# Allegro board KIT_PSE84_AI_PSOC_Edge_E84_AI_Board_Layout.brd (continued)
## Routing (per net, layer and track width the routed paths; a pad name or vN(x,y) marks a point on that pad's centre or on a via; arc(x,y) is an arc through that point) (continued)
RF_OUT: length 2
  TOP w0.127: C198.1 U25.50
ROSC_IN_80MHZ: length 2.2
  TOP w0.15: R102.2 21.77,17.37 22.28,17.89 U5.M2
RSPI_CLK: length 18.4
  TOP w0.089: v1(23.96,30.11) 24.24,30.39 U1.L7
  TOP w0.102: v2(30.57,19.06) 30.3,18.79 30.08,18.79 29.9,18.97
  TOP w0.15: U5.B1 28.83,19.29 29.58,19.29 29.9,18.97
  L03_SIG1 w0.089: v2(24.84,23.88) 24.84,25.57 24.52,25.89 24.52,28.46 24.29,28.7 24.29,29.78 v1(23.96,30.11)
  L05_PWR w0.102: v2(24.84,23.88) 25.78,22.94 25.93,22.94 26.14,22.73 26.14,22.58 28.95,19.77 30.27,19.77 30.49,19.55 30.49,19.55 30.57,19.47 v2(30.57,19.06)
RSPI_CS: length 27.1
  TOP w0.089: v1(21.26,35.94) 21.29,35.94 21.31,35.92 21.33,35.92 U1.C3
  TOP w0.15: v2(29.54,20.75) 29.54,20.77 29.23,21.08 27.63,21.08 27.48,20.93 27.48,20.22 26.59,19.33 26.37,19.33 U5.G1
  L03_SIG1 w0.089: v1(21.26,35.94) 20.99,35.67 20.99,35.15 21.18,34.96 21.45,34.96 21.64,34.77 21.64,34.49 21.82,34.31 22.1,34.31 22.29,34.12 22.29,33.85 22.48,33.66 23.81,33.66 24.43,33.04 24.69,33.04 24.96,32.77 24.96,32.3 24.86,32.21 24.86,31.92 24.99,31.79 24.99,31.31 24.64,30.95 24.64,30.54 24.87,30.31 24.87,28.63 24.93,28.58 24.93,26.96 24.94,26.96
  L03_SIG1 w0.102: v2(26.44,23.88) 26.17,24.15 26.17,25.54 25.68,26.04 25.18,26.04 24.94,26.28 24.94,26.68 24.94,26.96
  L05_PWR w0.102: v2(26.44,23.88) 29.27,21.05 29.27,21.02 v2(29.54,20.75)
RSPI_IRQ: length 15.9
  TOP w0.089: U1.N12 27.83,28.78 v1(27.83,28.75)
  TOP w0.15: U5.C1 28.64,19.6 29.85,19.6 30.05,19.39 v2(30.11,19.39)
  L03_SIG1 w0.089: 29.9,26.59 29.9,26.83 28.99,27.75 28.37,27.75 28.16,27.96 28.16,28.17 27.83,28.5 v1(27.83,28.75)
  L03_SIG1 w0.157: 29.9,26.59 30.53,25.97 30.53,23.88 30.74,23.67 30.74,21.69 31.3,21.13 31.3,19.79 31.09,19.58 30.3,19.58 30.11,19.39 v2(30.11,19.39)
RSPI_MISO: length 21.2
  TOP w0.089: v1(23.94,31.37) 23.91,31.37 U1.K6
  TOP w0.102: 29.51,20.17 29.99,20.17 30.13,20.03 30.47,20.03 30.56,19.94 v2(30.94,19.94)
  TOP w0.15: U5.E1 28.21,20.17 29.51,20.17
  L03_SIG1 w0.089: v2(25.66,23.88) 25.03,24.5 25.03,25.67 24.71,25.99 24.71,28.54 24.48,28.77 24.48,30.11 24.28,30.31 24.28,31.03 v1(23.94,31.37)
  L05_PWR w0.089: 26.06,23.09 26.06,23.46 25.92,23.6 25.92,23.61 v2(25.66,23.88)
  L05_PWR w0.102: v2(30.94,19.94) 30.67,20.21 28.94,20.21 26.06,23.09
RSPI_MOSI: length 45
  TOP w0.089: U1.C5 v1(22.62,35.94)
  TOP w0.15: U5.D1 28.39,19.85 29.95,19.85 30.01,19.8 30.28,19.8 30.61,19.47 30.89,19.47 31.05,19.31 31.05,19.14 30.98,19.06 v2(30.98,18.66)
  L03_SIG1 w0.089: v1(22.62,35.94) 22.62,36.13 22.29,36.45 22.29,36.73 22.1,36.92 21.83,36.92 20.76,37.99 20.16,37.99 20.08,37.91 19.43,37.91 19.13,37.61 19.13,35.85 20.68,34.31 21.45,34.31 21.64,34.12 21.64,33.85 21.84,33.66 22.1,33.66 22.29,33.47 22.29,33.2 22.48,33.01 22.75,33.01 23.15,33.41 23.6,33.41 23.9,33.1 v1(23.9,32.05)
  L04_SIG2 w0.089: 24.13,26.59 24.39,26.85 24.39,27.77 24.45,27.83 24.45,30.99 24.26,31.18 24.26,31.63 24.15,31.75 24.15,31.8 v1(23.9,32.05)
  L04_SIG2 w0.157: v2(21.02,20.04) 21.02,20.25 20.61,20.66 20.61,21 20.85,21.24 21.02,21.24 22.34,22.56 22.34,22.96 23.02,23.64 23.02,24.07 23.47,24.52 23.47,25.93 24.13,26.59
  L05_PWR w0.178: v2(30.98,18.66) 30.75,18.43 28.76,18.43 27.15,20.04 v2(21.02,20.04)
RXRES_L: length 9
  TOP w0.15: v2(28.98,20.68) 28.9,20.59 R101.1 ; U1.R12 27.56,27.75 27.56,27.38 27.84,27.1 v2(27.86,27.1)
  L03_SIG1 w0.102: v2(27.86,27.1) 28.21,26.76 28.21,26.3 29.35,25.16 29.35,24.8 29.77,24.38 29.77,24.03 29.41,23.67 29.41,23.24
  L03_SIG1 w0.157: v2(28.98,20.68) 28.98,22.82 29.41,23.24
SERIAL_INT0: length 21.1
  TOP w0.15: U1.L14 v1(29.12,30.09)
  L04_SIG2 w0.089: 31.17,30.46 30.89,30.46 30.52,30.09 v1(29.12,30.09)
  L04_SIG2 w0.157: 31.17,30.46 32.25,31.54 32.25,32.34 32.91,32.99 32.91,39.59 J5.5
  BOTTOM w0.15: J5.5 32.77,39.45 32.77,36.71 32.53,36.47 32.53,35.93 32.62,35.84 R192.1
SERIAL_INT1: length 18.9
  TOP w0.15: U1.M13 v1(28.49,29.41)
  L04_SIG2 w0.089: v1(28.49,29.41) 29.46,29.41
  L04_SIG2 w0.157: 29.46,29.41 29.8,29.41 30.05,29.66 31.26,29.66 31.37,29.77 32.35,29.77 32.51,29.93 32.51,32.23 33.17,32.89 33.17,37.31 J5.4
  BOTTOM w0.15: J5.4 33.1,37.24 33.1,34.86 32.92,34.69 R193.1
SERIAL_INT2: length 15.6
  TOP w0.15: U1.M14 29.09,29.47 29.64,29.47 29.82,29.29 v1(30.2,29.29)
  L04_SIG2 w0.089: 31.17,28.9 30.78,29.29 v1(30.2,29.29)
  L04_SIG2 w0.157: 31.17,28.9 31.62,28.45 32.01,28.45 32.41,28.85 32.41,29.39 32.89,29.87 32.89,31.49 33.43,32.02 33.43,35.03 J5.3
  BOTTOM w0.15: J5.3 34.42,35.04 33.27,33.89 R194.1
SERIAL_INT3: length 14
  TOP w0.15: U1.N13 28.47,28.79 v1(28.49,28.79)
  L04_SIG2 w0.089: 31.17,28.12 30.24,28.12 29.91,28.45 28.83,28.45 v1(28.49,28.79)
  L04_SIG2 w0.157: J5.2 35.36,32.54 35.36,30.55 34.7,29.89 33.85,29.89 33.29,29.33 33.29,29.15 32.26,28.12 31.17,28.12
  BOTTOM w0.15: J5.2 33.44,33.48 33.05,33.09 R195.1
SMIF0_CLKP: length 4.5
  BOTTOM w0.15: U4.B2 12.66,37.61 12.83,37.44 12.83,35.82 13.77,34.88 R61.1
SMIF0_CS: length 32.3
  TOP w0.15: v2(11.39,38.11) 10.33,39.17 R112.1 6.38,39.17 5.59,38.38 5.59,33.3 6.4,32.49 6.48,32.49 6.5,32.46 7.31,32.46 10.69,29.08 17.09,29.08 17.4,28.77 18.51,28.77 18.74,29 18.74,29.64 19,29.9 19,30.34 19.43,30.77 22,30.77 U1.K4
  BOTTOM w0.15: U4.C2 11.39,37.69 v2(11.39,38.11)
SMIF0_DATA0: length 7.1
  BOTTOM w0.15: U4.D3 10.3,39.03 10.45,39.18 10.7,39.18 10.85,39.03 10.85,35.76 11,35.61 11.51,35.61 12.04,35.08 R45.1
SMIF0_DATA1: length 4.6
  BOTTOM w0.15: R47.1 11.06,34.79 9.91,35.94 9.91,37.46 10.06,37.61 U4.D2
SMIF0_DATA2: length 8.2
  BOTTOM w0.15: U4.C4 11.05,39.61 10.9,39.76 10.9,40.03 11.05,40.18 11.26,40.18 11.84,39.6 11.84,35.82 12.83,34.82 12.83,33.88 R49.1
SMIF0_DATA3: length 7.7
  BOTTOM w0.15: U4.D4 9.81,39.12 9.04,39.12 8.5,38.57 8.5,35.99 10.16,34.33 R51.1
SMIF1_CLKN: length 12.8
  TOP w0.102: R63.2 16.97,33.82 16.75,34.04 16.12,34.04 15.83,34.34 15.72,34.34 v2(15.47,34.08) ; v2(8.91,36.16) 9.16,36.42 9.97,36.42 10.07,36.32 10.07,35.9 9.97,35.8 U3.B1
  L03_SIG1 w0.102: v2(15.47,34.08) 15.47,34.23 15.36,34.33 15.08,34.33 14.78,34.03 13.31,34.03 13.13,33.85 12.83,33.85 12.65,34.03 12.15,34.03 11.96,33.85 11.66,33.85 11.48,34.03 11.17,34.03 10.39,34.81 10.13,34.81 9.92,35.02 9.92,35.28 9.7,35.49 9.7,36.03 9.33,36.4 9.01,36.4 8.91,36.3 v2(8.91,36.16)
SMIF1_CLKP: length 12.8
  TOP w0.102: v2(15.47,34.85) 15.72,34.6 15.93,34.6 16.23,34.3 16.82,34.3 16.97,34.45 R62.2 ; U3.B2 10.43,35.8 10.33,35.9 10.33,36.42 10.07,36.67 9.16,36.67 v2(8.91,36.93)
  L03_SIG1 w0.102: v2(15.47,34.85) 15.47,34.71 15.36,34.61 14.96,34.61 14.66,34.31 11.28,34.31 9.98,35.61 9.98,36.15 9.44,36.69 9.01,36.69 8.91,36.79 v2(8.91,36.93)
SMIF1_CS: length 32.3
  TOP w0.15: U1.C4 21.98,35.92 v1(21.95,35.92) ; U3.A3 11.35,36.8 10.68,37.46 7.9,37.46 7.73,37.29 R114.1 6.68,37.29 5.84,36.45 5.84,33.48 6.6,32.72 7.44,32.72 9.8,30.36 v2(11.56,30.36)
  L04_SIG2 w0.089: 20.76,36.21 20.84,36.29 21.45,36.29 21.64,36.48 21.64,36.83 21.73,36.92 22.1,36.92 22.29,36.73 22.29,36.25 22.2,36.17 22.2,36.17 v1(21.95,35.92)
  L04_SIG2 w0.157: 20.76,36.21 18.94,36.21 16.26,33.53 16.26,33.36 15.95,33.05 15.95,32.1 15.5,31.65 12.85,31.65 v2(11.56,30.36)
SMIF1_DATA0: length 11.5
  TOP w0.15: v2(15.75,37.29) 16.23,37.77 R46.2 ; v1(12.35,36.13) 12.17,35.95 12.17,34.7 11.7,34.23 U3.D3
  L03_SIG1 w0.157: v2(15.75,37.29) 15.67,37.36 13.59,37.36 13.31,37.64 11.13,37.64 10.95,37.46 10.95,37.19 11.11,37.03 12.12,37.03 12.34,36.81 12.34,36.52 12.35,36.51 v1(12.35,36.13)
SMIF1_DATA1: length 12.6
  TOP w0.15: R48.2 16.88,37.06 16.38,37.06 16.11,36.78 15.45,36.78 v2(15.32,36.91) ; v1(11.16,35.23) 11.1,35.17 11.1,34.7 10.7,34.3 U3.D2
  L03_SIG1 w0.157: v1(11.16,35.23) 11.16,35.33 10.38,36.1 10.38,36.31 9.87,36.82 9.87,37.04 10.06,37.24 10.29,37.24 10.89,36.64 11.32,36.64 11.69,36.26 11.69,36.21 12.17,35.73 12.5,35.73 12.69,35.92 13.49,35.92 13.87,36.3 13.87,36.38 14.33,36.84 14.41,36.84 14.48,36.91 v2(15.32,36.91)
SMIF1_DATA2: length 11.2
  TOP w0.15: v2(16.01,36.35) 16.01,36.24 16.44,35.82 16.65,35.82 16.97,36.14 R50.2 ; v1(13.21,34.88) 13.21,35.23 13.06,35.38 12.85,35.38 12.7,35.23 U3.C4
  L03_SIG1 w0.157: v1(13.21,34.88) 12.83,34.88 12.7,34.75 11.81,34.75 11.65,34.91 11.65,35.13 11.81,35.29 13.07,35.29 13.29,35.51 13.7,35.51 13.92,35.29 14.23,35.29 14.49,35.55 14.49,35.77 14.27,35.99 14.27,36.22 14.49,36.44 14.72,36.44 15.3,35.86 15.85,35.86 16.01,36.02 v2(16.01,36.35)
SMIF1_DATA3: length 11.6
  TOP w0.15: U3.D4 12.62,33.72 12.33,33.72 12.18,33.87 12.18,34.15 12.4,34.37 14.2,34.37 14.5,34.67 v1(14.5,34.77) ; v2(15.77,35.37) 15.66,35.26 15.3,35.26 15.19,35.15 14.25,35.15 14.07,35.33 14.07,35.61 14.25,35.79 14.71,35.79 14.86,35.94 14.86,36.27 15.01,36.42 15.27,36.42 15.45,36.24 15.45,35.94 15.62,35.78 15.94,35.78 16.18,35.54 16.18,35.41 16.34,35.25 16.85,35.25 R52.2
  L03_SIG1 w0.157: v1(14.5,34.77) 14.5,35 14.97,35.46 15.68,35.46 v2(15.77,35.37)
SMIF1_DATA4: length 11.7
  TOP w0.15: R54.2 v2(16.31,32.17) ; v1(14.33,33.66) 14.33,33.96 14.48,34.11 14.69,34.11 14.84,33.96 14.84,32.6 15.01,32.42 15.01,31.82 14.74,31.55 14.3,31.55 14.15,31.7 14.15,31.93 14.5,32.28 14.5,32.79 14.12,33.17 13.23,33.17 13.08,33.32 13.08,33.78 13.21,33.92 13.58,33.92 U3.D5
  L03_SIG1 w0.157: v2(16.31,32.17) 16.02,32.46 16.02,32.81 15.17,33.66 v1(14.33,33.66)
SMIF1_DATA5: length 11.4
  TOP w0.15: v1(12.27,32.39) 12.24,32.36 11.4,32.36 11.25,32.51 11.25,32.69 11.36,32.8 U3.E3 ; v2(15.24,32.76) 15.25,32.76 16.02,32.76 16.23,32.97 R56.2
  L03_SIG1 w0.157: v1(12.27,32.39) 12.8,32.39 12.91,32.28 12.91,32.1 12.64,31.83 12.3,31.83 11.63,32.49 11.63,32.85 12.37,33.58 12.57,33.58 12.85,33.3 12.85,33.08 13.01,32.92 13.32,32.92 13.48,33.08 13.48,33.27 13.64,33.43 13.99,33.43 14.16,33.26 14.75,33.26 v2(15.24,32.76)
SMIF1_DATA6: length 11.6
  TOP w0.15: R58.2 16.72,31.42 16.44,31.7 15.47,31.7 v2(15.04,31.27) ; U3.E2 v1(10.22,32.8)
  L03_SIG1 w0.157: v2(15.04,31.27) 14.45,31.85 13.79,31.85 12.7,30.76 12.23,30.76 11.75,31.24 10.95,31.24 9.68,32.51 9.68,33.49 9.79,33.61 10.04,33.61 10.19,33.45 10.19,32.82 v1(10.22,32.8)
SMIF1_DATA7: length 11.3
  TOP w0.15: v2(15.62,29.49) 15.9,29.77 R60.2 ; U3.E1 9.69,32.79 9.27,32.79 9.27,32.79 v1(9.22,32.79)
  L03_SIG1 w0.157: v1(9.22,32.79) 9.22,32.41 10.78,30.84 11.58,30.84 12.06,30.36 12.53,30.36 12.69,30.2 12.69,29.53 12.91,29.31 13.17,29.31 13.33,29.47 13.33,29.74 13.48,29.9 13.82,29.9 13.98,29.74 13.98,29.61 14.39,29.2 15.33,29.2 v2(15.62,29.49)
SMIF1_RWDS: length 12.4
  TOP w0.15: v2(15.83,31.24) 15.83,30.91 16.17,30.57 R65.2 ; U3.C3 11.7,34.76 11.32,34.38 11.32,33.56 v1(11.55,33.33)
  L03_SIG1 w0.157: v2(15.83,31.24) 14.81,32.25 14.81,32.62 14.57,32.86 13.98,32.86 13.72,32.59 13.72,32.34 12.65,31.27 12.28,31.27 11.32,32.24 10.82,32.24 10.64,32.41 10.64,33.15 10.83,33.33 v1(11.55,33.33)
USB_DEV_EN: length 21.6
  TOP w0.15: U31.4 14.9,14.23 15.05,14.08 15.05,13.87 15.02,13.83 v2(15.02,13.81) ; v2(15.43,19.17) 15.14,18.88 15.14,18.79 14.64,18.29 R219.1 ; Q3.5 17.44,6.48 17.98,7.02 17.98,8.25 17.62,8.61 17.17,8.61 16.54,7.98 v2(16.38,7.98)
  L03_SIG1 w0.157: v2(15.02,13.81) 15.02,15.56 14.76,15.83 14.76,17.2 15.43,17.87 v2(15.43,19.17)
  L04_SIG2 w0.157: v2(16.38,7.98) 16.09,8.27 16.06,8.27 15.59,8.74 15.59,9.68 14.78,10.49 14.78,13.17 15.02,13.41 v2(15.02,13.81)
  BOTTOM w0.15: v2(15.43,19.17) 15.43,19.13 15.58,18.97 U26.4 ; R191.2 17.15,7.21 17.12,7.18 16.78,7.18 16.38,7.58 v2(16.38,7.98)
USB_HOST_EN: length 19.4
  TOP w0.15: v2(14.52,13.5) 13.95,14.07 U31.3 ; U15.4 15.96,15.58 v2(15.82,15.44) 15.61,15.44 15.1,14.93 U31.6 ; v2(17.93,6.4) 18.01,6.48 Q3.2
  L03_SIG1 w0.157: v2(14.52,13.5) 14.81,13.21 15.31,13.21 15.46,13.36 15.46,15.08 v2(15.82,15.44)
  L04_SIG2 w0.157: v2(17.93,6.4) 18.36,6.83 18.36,8.31 17.55,9.12 17.07,9.12 15.37,10.82 15.37,11.56 15.46,11.65 15.46,15.08 v2(15.82,15.44)
  BOTTOM w0.15: v2(17.93,6.4) 17.81,6.28 R173.2
USB_V_SENSE: length 3.4
  BOTTOM w0.178: R27.2 R25.2 28.82,15.31 28.38,15.75 27.62,15.75 27.05,16.32 U2.19
USER_BTN: length 16.3
  TOP w0.15: U1.P3 v1(21.32,28.14) ; v2(16.46,23.34) 16.46,23.27 16.02,22.84 C57.1 15.58,22.84 15.47,22.73 SW1.2 SW1.1 9.73,22.73 9.63,22.64 R198.2
  L03_SIG1 w0.089: 20.6,26.59 21.07,27.06 21.07,27.89 v1(21.32,28.14)
  L03_SIG1 w0.157: v2(16.46,23.34) 17.14,24.02 19.54,24.02 20.37,24.85 20.37,25.99 20.6,26.23 20.6,26.59
USER_LED1: length 39.5
  TOP w0.15: Q7.G 30.51,7.61 30.71,7.42 R211.2 31.37,7.07 31.53,6.91 v2(31.54,6.91) ; U1.C14 29.12,35.94 29.83,35.94 29.96,36.07 30.52,36.07 30.66,35.93 30.66,35.14 31.12,34.69 31.91,34.69 32.79,33.81 32.79,32.86 33.37,32.28 33.37,30.08 34.54,28.91 34.54,28.53 35.16,27.91 35.16,24.36 34.18,23.38 32.81,23.38 32.28,22.85 32.28,22.47 31.75,21.93 31.75,19.99 v2(32.69,19.05)
  L04_SIG2 w0.157: v2(31.54,6.91) 31.14,7.31 31.14,12.57 32.74,14.17 32.74,16.56 32.26,17.04 32.26,18.62 v2(32.69,19.05)
USER_LED2: length 40.7
  TOP w0.15: v2(32.7,19.84) 32.29,19.84 32,20.13 32,21.83 32.53,22.36 32.53,22.74 32.92,23.12 34.28,23.12 35.41,24.25 35.41,28.13 34.85,28.69 34.85,29.16 35.4,29.71 35.4,31.81 34.9,32.31 33.76,32.31 33.04,33.02 33.04,33.94 32.04,34.94 31.2,34.94 30.9,35.24 30.9,36.69 30.69,36.91 29.44,36.91 U1.B14
  L04_SIG2 w0.157: v2(27.4,8.68) 27.4,9.37 32.16,14.12 32.16,15.75 31.75,16.16 31.75,18.89 v2(32.7,19.84)
  BOTTOM w0.15: v2(27.4,8.68) R212.2 26.55,8.68 26.46,8.59 Q8.G
USER_LED_RGB_B: length 20.5
  TOP w0.089: 28.12,26.59 28.22,26.7 28.22,26.95 28.23,26.95 28.23,27.25 28.22,27.26 28.22,27.28 27.9,27.6 27.9,28.05 U1.P12
  TOP w0.15: v2(27.51,25.4) 27.51,25.99 28.12,26.59
  BOTTOM w0.15: R215.2 33.05,14.6 33.03,14.58 32.83,14.58 32.58,14.33 Q11.G 31.5,14.32 31.11,14.71 31.11,15.57 31.65,16.1 31.65,18.62 31.97,18.94 31.97,19.79 31.5,20.27 31.5,21.74 30.94,22.3 30.94,24.38 30.2,25.12 28.52,25.12 28.24,25.4 v2(27.51,25.4)
USER_LED_RGB_G: length 19.2
  TOP w0.15: U1.R14 28.92,27.69 28.92,26.91 28.07,26.06 28.07,25.2 28.63,24.64 28.63,24.39 29.23,23.78 29.41,23.78 30.12,23.07 30.12,20.95 30.08,20.91 30.08,20.45 30.23,20.3 30.69,20.3 30.79,20.4 31.29,20.4 31.5,20.19 31.5,19.43 32.23,18.7 32.23,17.06 32.64,16.65 32.64,16.51 33.07,16.08 v2(35.2,16.08)
  BOTTOM w0.15: v2(35.2,16.08) 35.2,16.08 35.18,16.1 R214.2 33.72,16.1 33.72,16.1 Q10.G
USER_LED_RGB_R: length 21.9
  TOP w0.15: v2(30.5,15.9) 30.92,15.49 30.92,14.93 31.59,14.26 R213.2 31.59,13.63 31.72,13.5 Q9.G ; U1.P13 v1(28.5,28.11)
  L03_SIG1 w0.157: v2(32.54,21.72) 31.95,21.13 31.95,19.76 31.5,19.3 31.5,16.9 v2(30.5,15.9)
  L04_SIG2 w0.089: 29.18,26.59 29.18,27.97 29.04,28.11 v1(28.5,28.11)
  L04_SIG2 w0.157: v2(32.54,21.72) 31.72,21.72 31.66,21.78 30.06,21.78 29.73,21.44 29.05,21.44 28.43,22.07 28.43,24.14 28.93,24.64 28.93,25.88 29.18,26.14 29.18,26.59
USR_RGB_B: length 3.6
  BOTTOM w0.15: Q11.D 31.58,13.3 32.59,12.3 32.59,11.71 32.85,11.44 33.02,11.44 33.03,11.43 R165.2
USR_RGB_G: length 7.7
  TOP w0.15: v2(32.16,16.33) 31.6,16.33 31.17,15.9 31.17,15.04 32.18,14.02 32.18,12.42 31.55,11.79 31.12,11.79 30.95,11.61 R157.1
  BOTTOM w0.15: v2(32.16,16.33) 32.16,16.25 32.27,16.15 Q10.D
USR_RGB_R: length 2.8
  TOP w0.15: Q9.D 30.76,12.18 30.48,11.89 30.48,10.78 30.95,10.31 R156.1
VTARG_MEAS: length 2.3
  BOTTOM w0.178: U2.32 21.85,16.1 21.65,15.91 R24.2 R23.2
WCO_IN: length 14.9
  TOP w0.15: v2(30.37,38.26) 29.67,38.96 C60.2 29.67,39.45 30.07,39.85 Y2.1 ; U1.H8 25.19,32.07 v1(25.19,32.06)
  L04_SIG2 w0.089: v2(30.37,38.26) 30.76,37.87 30.76,34.79 30.99,34.56 30.99,33.73 29.84,32.59 26.49,32.59 26.19,32.29 26.19,31.9 26,31.71 25.56,31.71 25.46,31.81 25.44,31.81 v1(25.19,32.06)
WCO_OUT: length 14.8
  TOP w0.15: U1.G7 v1(24.6,32.65) ; v2(29.76,38.32) 29.32,38.32 28.95,38.68 C59.2 28.95,39.77 28.87,39.86 Y2.2
  L04_SIG2 w0.089: v1(24.6,32.65) 24.95,32.65 25.06,32.77 29.72,32.77 30.33,33.38 30.33,34.57 30.58,34.82 30.58,37.5 v2(29.76,38.32)
WL_BT_DEV_WAKE: length 23
  TOP w0.15: v2(20.34,47.88) R103.2 U25.5 ; v1(29.87,34.55) 29.85,34.57 29.7,34.57 U1.E15
  L04_SIG2 w0.089: v1(29.87,34.55) 29.87,35.05 29.67,35.26 29.67,37.19 29.01,37.84 28.81,37.84 27.76,38.89 27.76,39.29
  L04_SIG2 w0.157: 27.76,39.29 27.76,45.95 26.14,47.58 20.64,47.58 v2(20.34,47.88)
WL_HOST_WAKE: length 23.2
  TOP w0.15: v2(20.6,49.51) 20.34,49.26 R104.2 U25.2 ; v1(28.47,33.95) 28.44,33.95 U1.F13
  L03_SIG1 w0.089: 26.9,39.24 26.9,37.42 26.84,37.37 26.84,37.1 27.03,36.91 27.33,36.91 27.49,36.75 27.49,35.15 27.68,34.96 27.95,34.96 28.14,34.77 28.14,34.28 v1(28.47,33.95)
  L03_SIG1 w0.102: 26.9,39.24 26.9,39.45
  L03_SIG1 w0.157: 26.9,39.45 26.9,41.35 24.41,43.84 23.65,43.84 23.19,44.3 23.19,48.72 22.39,49.51 v2(20.6,49.51)
WL_REG_ON: length 23.4
  TOP w0.15: U25.9 21.34,45.19 20.96,44.81 R108.2 20.34,45.26 20.21,45.39 v2(19.61,45.39) ; U1.F14 v1(29.12,33.99)
  L04_SIG2 w0.089: v1(29.12,33.99) 28.79,34.31 28.33,34.31 28.14,34.5 28.14,35.42 28.33,35.61 28.6,35.61 28.79,35.8 28.79,36.72 28.6,36.91 28.33,36.91 28.14,37.1 28.14,37.77 27.1,38.82 27.1,39.29
  L04_SIG2 w0.157: v2(19.61,45.39) 20.25,45.39 20.27,45.37 26.36,45.37 27.1,44.62 27.1,39.29
WL_SDIO_CLK: length 2.4
  TOP w0.15: v2(24.33,42.29) 24.5,42.29 24.82,42.61 U25.20
  BOTTOM w0.15: v2(24.33,42.29) 24.33,42.7 24.66,43.02 R38.2
WL_SDIO_CMD: length 5.4
  TOP w0.15: U25.15 22.32,42.54 22.1,42.32 19.91,42.32 18.26,43.97 R33.2
WL_SDIO_DATA0: length 5
  TOP w0.15: R37.2 18.51,44.66 18.51,44.32 20.26,42.57 21.48,42.57 21.82,42.91 U25.14
WL_SDIO_DATA1: length 5.7
  TOP w0.15: U25.16 22.82,42.53 22.35,42.07 19.65,42.07 18.59,43.13 R36.2
WL_SDIO_DATA2: length 6
  TOP w0.15: R35.2 19.02,42.27 19.48,41.81 22.52,41.81 23.32,42.61 U25.17
WL_SDIO_DATA3: length 6.5
  TOP w0.15: R34.2 19.08,41.43 19.2,41.56 22.77,41.56 23.82,42.61 U25.18
N17461053: length 8.7
  TOP w0.15: v2(19.84,13.13) 20.13,13.42 20.13,13.58 21.56,15.01 21.56,15.36 22.6,16.39 U5.M5
  BOTTOM w0.15: v2(19.84,13.13) 19.55,13.42 19.55,15.91 TP21.1
N17461288: length 2.2
  TOP w0.15: U5.L1 23.43,20.17 23.37,20.23 C72.2
N17462113: length 8.1
  TOP w0.229: v3(16.46,15.84) 16.46,15.99 16.43,16.02 16.43,17.45 16.66,17.68 U24.4
  BOTTOM w0.229: v3(16.46,15.84) 16.06,15.84 16.01,15.89 15.64,15.89 15.3,15.55 15.3,15.03 15.61,14.72 C80.1 16.8,14.72 17.01,14.92 C79.1 18.4,14.92 18.43,14.95 FB4.2
N17462137: length 1.4
  TOP w0.15: R102.1 19.67,17.37 19.36,17.68 U24.3
N17489317: length 5.8
  TOP w0.15: SW1.4 SW1.3 10.28,20.34 R73.2
N17506591: length 2.1
  TOP w0.15: R85.1 21.38,22.54 21.18,22.35 21.18,21.78 20.88,21.48 U18.1
N17580471: length 1.7
  BOTTOM w0.15: C43.1 22.18,25.68 21.45,24.95 U2.53
N17581080: length 1.9
  BOTTOM w0.15: C52.1 19.36,19.89 19.72,20.24 U2.42
N17581130: length 2.4
  BOTTOM w0.114: R26.2 26.55,14.93 26.39,15.09 26.39,15.37 26.08,15.69 25.87,15.69 25.76,15.8 25.76,16.02 25.85,16.11 U2.22
N17581131: length 2.4
  BOTTOM w0.114: R28.2 25.93,14.93 26.16,15.16 26.16,15.28 25.99,15.46 25.78,15.46 25.53,15.71 25.53,16.02 25.45,16.11 U2.23
N17581135: length 1.6
  BOTTOM w0.15: U2.31 22.25,15.79 22.47,15.57 C53.1
N17604769: length 3
  TOP w0.15: R101.2 27.84,20.23 26.49,18.87 26.41,18.87 U5.F1
N17606878: length 0.8
  TOP w0.15: R30.1 LED4.A
N17691977: length 5.2
  TOP w0.229: L4.1 29.53,41.77 29.11,41.35 28.5,41.35 28.49,41.35 C92.1 27.51,41.84 27.32,42.03 U25.25
N17691999: length 4.5
  TOP w0.229: U25.28 30.9,44.19 31.13,43.96 L4.2
N17694386: length 23.1
  L03_SIG1 w0.254: v3(7.44,30.58) 7.44,30.08 v3(5.84,28.47) 7.66,26.65 7.66,21.42 6.38,20.13 6.38,19.47 6.34,19.43 6.34,19.43 5.61,18.71 5.61,13.39 v3(5.96,13.04)
  BOTTOM w0.15: v3(7.44,30.58) 7.64,30.38 U28.26 ; U28.22 5.99,28.28 5.84,28.43 v3(5.84,28.47)
  BOTTOM w0.229: v3(5.96,13.04) 5.18,13.04 5,13.23 J8.1
N17694402: length 17.5
  L03_SIG1 w0.254: v3(5.84,26.75) 7.2,25.38 7.2,21.61 5.92,20.32 5.92,19.66 5.88,19.62 5.88,19.62 5.13,18.87 v3(5.13,15.99)
  L04_SIG2 w0.381: v3(5.84,26.75) 6.33,27.24 6.33,28.68 5.87,29.14 v3(5.8,29.14)
  BOTTOM w0.15: v3(5.84,26.75) 5.84,26.75 5.88,26.78 U28.19 ; v3(5.8,29.14) 5.86,29.14 6.22,28.78 U28.23
  BOTTOM w0.381: J8.2 5.13,15.23 v3(5.13,15.99)
N17694449: length 2.3
  BOTTOM w0.15: R123.1 10.04,31.81 10.19,31.66 C100.1 10.19,30.88 10.14,30.84 U28.31
N17694464: length 3
  BOTTOM w0.15: TP22.1 7.59,31.73 7.59,31.04 8.14,30.49 U28.27
N17694501: length 3.8
  BOTTOM w0.15: TP23.1 9.64,32.96 U28.30
N17694590: length 0.9
  BOTTOM w0.15: TP24.1 9.43,23.5 9.28,23.65 C105.1
N17694592: length 1
  BOTTOM w0.15: C105.2 8.79,24.51 8.64,24.66 U28.13
N17694611: length 1
  BOTTOM w0.15: C106.2 7.98,24.21 7.98,24.46 8.14,24.63 U28.14
N17694617: length 1.3
  BOTTOM w0.15: TP25.1 7.19,23.65 C106.1
N17695662: length 10.2
  BOTTOM w0.102: C119.1 10.06,49.69 9.9,49.53 9.42,49.53 R127.2 ; C119.1 R126.2 ; C119.1 10.71,49.69 10.86,49.54 11.25,49.54 11.45,49.74 R125.2 11.63,49.61 12.29,49.61 12.5,49.81 C115.1 12.7,49.63 13.02,49.63 13.18,49.8 13.18,50.72 13.94,51.49 13.94,53.08 14.19,53.33 14.52,53.33 R128.1
N17695725: length 1.1
  BOTTOM w0.102: C117.2 7.96,49.54 8.26,49.54 R127.1
N17695747: length 5.9
  BOTTOM w0.102: U10.1 4.88,53.42 4.98,53.32 5.42,53.32 5.69,53.04 5.69,51.13 5.18,50.62 5.18,49.64 5.28,49.54 5.44,49.54 R129.1
N17695749: length 1
  BOTTOM w0.102: R129.2 6.59,49.54 6.86,49.54 C117.1
N17695799: length 5.9
  BOTTOM w0.102: R130.1 5.44,49.28 5.18,49.28 4.93,49.53 4.93,50.73 5.44,51.24 5.44,52.94 5.31,53.06 5,53.06 4.88,52.94 U10.3
N17695801: length 1
  BOTTOM w0.102: C120.1 6.87,49.28 6.58,49.28 R130.2
N17695803: length 1.1
  BOTTOM w0.102: R131.1 8.26,49.28 7.96,49.28 C120.2
N17695815: length 9.4
  BOTTOM w0.102: R132.1 14.52,53.07 14.3,53.07 14.2,52.97 14.2,51.38 13.44,50.62 13.44,49.69 13.12,49.38 12.78,49.38 C122.2 12.29,49.35 11.68,49.35 11.47,49.14 R133.1 11.12,49.14 10.98,49.28 10.77,49.28 10.62,49.14 C119.2 10.11,49.14 9.97,49.27 9.4,49.27 R131.2
N17695981: length 6.8
  BOTTOM w0.102: R135.2 R136.2 26.2,53.06 25.53,53.06 25.45,52.99 C127.1 25.15,53.04 24.19,53.04 R134.2 23.9,53.11 22.97,53.11 C123.1 22.6,53.06 21.18,53.06 R137.1
N17696044: length 1.1
  BOTTOM w0.102: R136.1 27.29,53.12 27.59,53.12 C125.2
N17696066: length 2.2
  BOTTOM w0.102: U9.1 31.63,52.94 31.53,53.04 30.99,53.04 30.91,53.12 30.49,53.12 R138.1
N17696068: length 1.4
  BOTTOM w0.102: R138.2 29.34,53.12 28.69,53.12 C125.1
N17696118: length 2.2
  BOTTOM w0.102: U9.3 31.63,53.4 31.53,53.29 31.09,53.29 31.01,53.37 30.49,53.37 R139.1
N17696120: length 1.4
  BOTTOM w0.102: C128.1 28.69,53.37 29.34,53.37 R139.2
N17696122: length 1.1
  BOTTOM w0.102: R140.1 27.29,53.37 27.59,53.37 C128.2
N17696134: length 6.7
  BOTTOM w0.102: R141.1 20.98,53.42 21.08,53.32 21.38,53.32 21.54,53.47 21.84,53.47 21.99,53.32 22.47,53.32 C130.2 23,53.37 23.87,53.37 R142.1 24.37,53.29 24.81,53.29 24.95,53.44 25.1,53.44 C127.2 25.36,53.54 25.58,53.32 26.31,53.32 26.42,53.42 R140.2
N17699019: length 21.4
  TOP w0.15: U1.F7 v1(23.92,33.99) ; U1.A7 v1(23.92,37.24) ; U1.G4 v1(21.97,33.34) ; U1.P10 v1(26.52,28.14) ; U1.B8 v1(25.22,36.59)
  L05_PWR w0.089: v1(21.97,33.34) 22.29,33.66 22.75,33.66 23.6,33.66 v1(23.92,33.99) 24.27,33.99 24.82,34.53 24.82,36.18 v1(25.22,36.59) 25.54,36.26 25.54,35.76 25.72,35.58 25.99,35.58 26.18,35.39 26.18,34.88 26.22,34.84 26.22,33.82 25.54,33.14 25.54,31.25 25.35,31.06 25.08,31.06 24.89,30.87 24.89,30.6 25.09,30.41 25.35,30.41 25.54,30.22 25.54,29.95 25.54,29.33 25.77,29.11 25.88,29.11 25.88,29.11 26,29.11 26.19,28.92 26.19,28.46 v1(26.52,28.14)
  L05_PWR w0.157: v1(23.92,37.24) 24.57,37.24 v1(25.22,36.59)
  BOTTOM w0.15: v1(23.92,37.24) 23.65,37.51 FB8.2
N17699233: length 17.3
  L03_SIG1 w0.157: v2(35.05,23.32) 35.05,28.41 32.92,30.54 v2(32.92,32.02)
  L04_SIG2 w0.157: v2(35.05,23.32) 32.79,23.32 32.66,23.19 30.66,23.19 30.4,22.94 30.11,22.94 30.03,22.86 v2(29.62,22.86)
  BOTTOM w0.15: v2(29.62,22.86) 29.62,22.86 29.68,22.92 29.68,22.98 29.74,23.04 29.74,23.25 29.89,23.4 R226.2 ; v2(32.92,32.02) 32.64,32.02 32.49,31.87 FB9.1
N17699382: length 2.3
  TOP w0.15: U1.A12 v1(27.82,37.24)
  BOTTOM w0.15: v1(27.82,37.24) 27.86,37.24 28.67,38.04 L5.1
N17699478: length 7.5
  TOP w0.15: v3(25.41,25.48) 24.84,26.05 24.84,27.06 24.62,27.28 24.62,29.15 24.34,29.44 v1(23.92,29.44) U1.M7
  BOTTOM w0.15: v1(23.92,29.44) 24.12,29.23 C154.1 C153.1 ; v3(25.41,25.48) 25.71,25.78 R154.1
N17699488: length 2.7
  TOP w0.15: U1.K14 29.09,30.76 v1(29.13,30.76)
  BOTTOM w0.089: v1(29.13,30.76) 29.17,30.76 29.78,30.15 TP46.1 30.38,30.87 C155.1
N17701248: length 33.3
  TOP w0.15: C158.1 25.96,37.98 v1(25.21,37.23) U1.A8 ; U1.F12 v1(27.82,33.99) ; U1.K3 v1(21.94,31.35)
  L04_SIG2 w0.089: v1(25.21,37.23) 25.58,37.59 26.62,37.59 26.84,37.37 26.84,35.26 26.84,35.26 26.84,35.15 27.04,34.96 27.3,34.96 27.49,34.77 27.49,34.31 v1(27.82,33.99)
  L05_PWR w0.089: v1(21.94,31.35) 22.94,30.35 22.94,29.95 23.13,29.76 24.05,29.76 24.05,29.76 24.24,29.57 24.24,29.57 24.85,28.96 24.85,26.79 25.01,26.63 ; 31.17,32.89 29.44,32.89 28.79,33.55 28.79,34.12 28.62,34.29 28.12,34.29 v1(27.82,33.99) ; 26.74,26.59 26.76,26.59 27.95,27.78 28.63,27.78 29.49,28.64 29.49,29.72 30.17,30.4 30.17,30.78 30.91,31.52 31.17,31.52
  L05_PWR w0.152: 26.74,26.59 26.51,26.37 25.27,26.37 25.01,26.63
  L05_PWR w0.229: 31.17,32.89 31.66,32.4 31.66,32.02 31.17,31.52
  BOTTOM w0.178: C157.1 20.35,30.99 21.57,30.99 v1(21.94,31.35)
N17701334: length 0.5
  TOP w0.15: U1.C9 v1(25.87,35.94)
N17701356: length 56
  TOP w0.15: U1.E13 v1(28.47,34.64) ; U1.A6 v1(23.27,37.24) ; v1(21.46,27.38) 21.64,27.56 U1.R3 ; v3(30.45,27.64) 30.14,27.95 30.14,28.25 29.61,28.79 v1(29.12,28.79) U1.N14 ; v1(23.27,34.64) 23.3,34.61 23.3,34.61 U1.E6 ; U1.B2 v1(20.67,36.59)
  TOP w0.229: v1(20.67,36.59) 19.06,38.19 FB10.1 19.23,39.45 20.17,39.45 21.8,37.82 22.68,37.82 v1(23.27,37.24)
  L05_PWR w0.089: 24.41,26.59 24.41,27.43 24.07,27.77 21.85,27.77 v1(21.46,27.38) 21.22,27.14 20.56,27.14 20.34,27.35 20.34,35.08 20.87,35.61 21.45,35.61 21.64,35.42 21.64,35.15 21.83,34.96 22.94,34.96 23.02,34.88 23.03,34.88 v1(23.27,34.64) 23.52,34.88 23.52,34.89 23.61,34.97 23.61,35.37 23.85,35.61 24.08,35.61 24.27,35.8 24.27,36.07 24.08,36.26 23.79,36.26 23.61,36.43 23.61,36.89 v1(23.27,37.24) ; 31.17,30.91 30.96,30.7 29.88,29.62 29.88,29.15 30.07,28.96 30.07,28.02 v3(30.45,27.64) 29.79,26.98 28.3,26.98 27.91,26.59 ; 31.17,33.33 29.93,33.33 29.49,33.77 29.49,34.72 29.25,34.96 28.79,34.96 v1(28.47,34.64)
  L05_PWR w0.229: 27.91,26.59 27.22,25.9 25.11,25.9 24.41,26.59 ; 31.17,33.33 31.7,33.33 32.16,32.87 32.16,31.88 31.28,31 31.25,31 31.17,30.91
  BOTTOM w0.15: v1(29.12,28.79) 29.12,28.12 C160.1 ; v1(23.27,37.24) 23.27,37.55 C164.1 ; v1(20.67,36.59) 20.67,36.58 C161.1 ; C163.1 21.31,27 21.46,27.15 v1(21.46,27.38)
N17701674: length 9.4
  TOP w0.15: U1.M3 v1(21.32,29.44) ; U1.E3 v1(21.32,34.64) ; U1.G3 v1(21.32,33.34) ; U1.J3 v1(21.32,31.39)
  L05_PWR w0.089: v1(21.32,29.44) 20.98,29.77 20.98,31.05 v1(21.32,31.39) 20.83,31.88 20.83,32.84 v1(21.32,33.34) 20.98,33.67 20.98,34.42 21.2,34.64 v1(21.32,34.64)
  BOTTOM w0.15: C173.1 20.2,34.68 FB11.1
N17701770: length 6.4
  TOP w0.15: U1.J6 v1(23.27,31.39)
  BOTTOM w0.15: v1(23.27,31.39) 23.26,31.39 22.61,30.74 20.75,30.74 19.99,29.97 19.48,29.97 19.26,30.2 19.26,30.93 19.18,31.01 R155.1
N17701786: length 7.4
  TOP w0.15: C177.1 25.2,39.51 25.14,39.45 C178.1 ; v1(23.27,35.92) 23.28,35.92 U1.C6 ; U1.B7 23.94,36.56 v1(23.94,36.59) ; v1(23.94,35.94) 23.94,35.91 U1.C7
  TOP w0.178: C178.1 25.14,38.28 24.59,37.72 24.59,36.6 U1.B7
  BOTTOM w0.15: C176.1 24.17,35.71 v1(23.94,35.94) ; v1(23.27,35.92) 23.28,35.94 v1(23.94,35.94) ; v1(23.94,35.94) v1(23.94,36.59)
N17708163: length 23.1
  TOP w0.15: U1.J5 v1(22.62,31.39) ; R33.1 17.03,44.02 v2(16.83,43.81)
  L04_SIG2 w0.089: 24.66,37.92 24.66,33.91 24.24,33.5 24.24,33.12 23.5,32.38 23.02,32.38 22.88,32.52 21.81,32.52 21.64,32.35 21.64,31.9 21.83,31.71 22.29,31.71 v1(22.62,31.39)
  L04_SIG2 w0.157: v2(16.83,43.81) 17.4,43.81 18.41,42.8 22.89,42.8 23.8,41.89 23.8,38.79 24.66,37.92
N17708171: length 22
  TOP w0.15: v2(17.14,41.79) 17.14,41.61 17.32,41.43 R34.1 ; U1.F5 v1(22.62,33.99)
  L04_SIG2 w0.089: 21.54,38.05 23.13,38.05 23.59,37.58 23.59,37.1 23.61,37.09 23.61,35.17 23.4,34.96 23.07,34.96 22.93,34.82 22.93,34.3 v1(22.62,33.99)
  L04_SIG2 w0.157: v2(17.14,41.79) 18.28,41.79 18.95,41.12 18.95,40.75 19.11,40.6 20.16,40.6 20.32,40.44 20.32,40.12 20.16,39.97 19.11,39.97 18.95,39.81 18.95,38.96 17.82,37.83 17.82,37.57 18.15,37.23 18.41,37.23 19.33,38.15 19.33,38.91 19.8,39.38 20.21,39.38 21.54,38.05
N17708201: length 22.4
  TOP w0.15: U1.F4 v1(21.97,33.99) ; v2(16.66,42.32) 17.12,42.32 17.17,42.27 R35.1
  L04_SIG2 w0.089: 22.99,39.14 24.49,37.64 24.49,34.09 23.48,33.09 23.13,33.09 22.89,32.85 21.73,32.85 21.64,32.94 21.64,33.66 v1(21.97,33.99)
  L04_SIG2 w0.157: 22.99,39.14 22.99,41.99 22.53,42.44 18.16,42.44 17.3,43.31 16.77,43.31 16.61,43.15 16.61,42.78 16.66,42.73 v2(16.66,42.32)
N17708259: length 22.6
  TOP w0.15: v2(17.07,42.85) 17.07,42.98 17.22,43.13 R36.1 ; U1.G5 v1(22.62,33.34)
  L04_SIG2 w0.089: v1(22.62,33.34) 23.39,33.34 23.59,33.55 23.59,34.12 23.78,34.31 24.15,34.31 24.31,34.47 24.31,37.39 23.94,37.76
  L04_SIG2 w0.157: v2(17.07,42.85) 17.07,42.44 17.42,42.09 19.37,42.09 20.65,40.8 20.65,39.4 20.96,39.09 21.39,39.09 21.71,39.41 21.71,39.64 21.55,39.79 21.42,39.79 21.26,39.95 21.26,40.27 21.42,40.42 21.78,40.42 21.97,40.61 21.97,41.55 22.15,41.73 22.44,41.73 22.6,41.58 22.6,39.1 23.94,37.76
N17708293: length 23.4
  TOP w0.15: R37.1 16.94,44.91 v2(16.54,45.31) ; U1.D5 v1(22.62,35.29)
  L04_SIG2 w0.089: 22.36,37.62 22.69,37.62 22.94,37.37 22.94,35.61 v1(22.62,35.29)
  L04_SIG2 w0.157: v2(16.54,45.31) 16.08,44.86 16.08,41.99 16.71,41.35 18.11,41.35 18.62,40.84 18.62,39.09 16.85,37.32 16.85,36.96 17.58,36.22 17.98,36.22 19.61,37.85 19.61,38.5 19.76,38.66 20.27,38.66 21.31,37.62 22.36,37.62
N17708327: length 13.1
  TOP w0.15: U1.H5 v1(22.62,32.04)
  L04_SIG2 w0.089: 24.28,39.29 24.28,39.17 24.87,38.58 24.87,38.01 24.88,38.01 24.88,37.84 24.85,37.81 24.85,33.54 24.89,33.5 24.89,33.23 24.66,32.99 24.39,32.99 23.78,32.38 23.76,32.38 23.41,32.04 v1(22.62,32.04)
  L04_SIG2 w0.157: 24.28,39.29 24.28,41.3 v2(24.84,41.86)
  BOTTOM w0.15: R38.1 25.17,42.19 v2(24.84,41.86)
N17708399: length 3.2
  TOP w0.15: U1.P14 29.17,28.08 29.17,26.12 TP69.1
N17708861: length 13.3
  TOP w0.15: U1.N2 20.69,28.8 19.97,28.8 v1(19.7,28.53)
  L03_SIG1 w0.089: 18.72,29.08 18.77,29.08 19.32,28.53 v1(19.7,28.53)
  L03_SIG1 w0.157: v2(15.09,30.43) 15.83,30.43 16.43,29.82 17.98,29.82 18.72,29.08
  BOTTOM w0.15: v2(15.09,30.43) 15.27,30.25 15.76,30.25 15.95,30.44 15.95,30.69 15.8,30.83 15.66,30.83 15.66,30.84 14.9,30.84 14.63,31.1 14.63,31.38 13.89,32.13 13.09,32.13 12.04,33.17 R45.2
N17708863: length 4.3
  TOP w0.15: R46.1 18.29,37.77 20.12,35.94 20.66,35.94 U1.C2
N17708893: length 15.9
  TOP w0.15: U1.P1 v1(20.02,28.14)
  L03_SIG1 w0.157: v1(20.02,28.14) 19.75,27.86 19.03,27.86 18.19,27.03 17.33,27.03 17.16,27.2 17.16,27.6 17.32,27.76 18.05,27.76 18.21,27.92 18.21,28.65 18.05,28.8 16.89,28.8 15.79,29.9 14.71,29.9 v2(14.05,30.56)
  BOTTOM w0.15: v2(14.05,30.56) 14.05,30.95 14.12,31.03 14.12,31.36 13.73,31.75 12.38,31.75 11.36,32.77 11.36,32.98 11.11,33.23 R47.2
N17708895: length 3.3
  TOP w0.15: U1.C1 19.92,35.61 18.56,36.97 R48.1
N17708925: length 12.2
  TOP w0.15: v1(19.67,29.05) 19.74,29.11 U1.N1
  L03_SIG1 w0.157: v2(15.57,32.28) 15.57,32.26 16.27,31.56 16.5,31.56 16.99,32.05 17.26,32.05 17.43,31.88 17.43,31.6 16.92,31.09 16.92,30.82 17.1,30.63 18.85,30.63 19.67,29.81 v1(19.67,29.05)
  BOTTOM w0.15: v2(15.57,32.28) 15.17,31.88 14.75,31.88 14.61,32.03 14.61,32.74 14.45,32.9 13.64,32.9 13.61,32.93 13.18,32.93 R49.2
N17708927: length 4.7
  TOP w0.15: R50.1 17.83,36.43 18.72,36.43 18.9,36.25 18.9,36.04 18.78,35.92 18.78,35.71 18.99,35.49 19.2,35.49 19.32,35.61 19.53,35.61 19.84,35.31 20.65,35.31 U1.D2
N17708957: length 12.8
  TOP w0.15: U1.M2 20.68,30.07 19.92,30.07 19.33,29.48 19.11,29.48 v1(19.11,29.49)
  L03_SIG1 w0.157: v2(13.71,31.19) 13.72,31.19 13.99,31.19 14.32,30.86 15.63,30.86 15.66,30.83 15.99,30.83 16.58,30.23 18.36,30.23 v1(19.11,29.49)
  BOTTOM w0.15: v2(13.71,31.19) 13.54,31.37 12.22,31.37 10.98,32.61 10.98,32.65 10.41,33.23 R51.2
N17708959: length 4.3
  TOP w0.15: U1.D1 19.97,34.96 19.82,34.81 19.82,34.52 19.67,34.37 19.37,34.37 19.22,34.52 19.22,34.81 19.07,34.96 18.99,34.96 18.19,35.76 17.71,35.76 17.57,35.63 R52.1
N17708991: length 4.2
  TOP w0.15: U1.F2 20.94,33.61 20.94,33.38 20.52,32.97 19.31,32.97 18.95,32.61 18.18,32.61 17.74,32.17 R54.1
N17709023: length 4.5
  TOP w0.15: R56.1 17.95,33.35 18.33,33.35 18.48,33.2 18.48,33.18 18.63,33.03 18.93,33.03 19.08,33.18 19.08,33.2 19.23,33.35 20.47,33.35 20.68,33.56 20.68,34 U1.E2
N17709055: length 4.4
  TOP w0.15: U1.G2 20.62,32.64 19.53,32.64 19.13,32.23 18.34,32.23 18.11,32 18.11,31.86 17.62,31.37 R58.1
N17709075: length 4.7
  TOP w0.15: U1.H2 20.63,32 19.81,32 19.1,31.29 19.1,31.09 18.39,30.38 18.39,30.25 17.91,29.77 R60.1
N17709105: length 16.1
  TOP w0.15: U1.M1 20.66,29.44 v1(20.68,29.44)
  L03_SIG1 w0.157: v2(15.9,33.5) 15.9,33.68 16.08,33.86 16.3,33.86 16.63,33.54 16.63,33.31 16.46,33.15 16.46,32.93 16.69,32.7 16.91,32.7 17.07,32.87 17.29,32.87 17.83,32.33 17.83,31.89 18.41,31.32 19.58,31.32 20.68,30.23 v1(20.68,29.44)
  BOTTOM w0.15: v2(15.9,33.5) 15.98,33.58 16.3,33.58 16.48,33.76 16.48,34.09 16.63,34.24 16.92,34.24 17.07,34.09 17.07,33.73 17.22,33.58 17.35,33.58 17.48,33.45 17.48,33.2 17.35,33.07 16.75,33.07 16.58,32.89 16.58,32.74 16.43,32.59 16.15,32.59 15.98,32.76 15.98,32.89 15.83,33.04 15.58,33.04 15.34,33.28 13.8,33.28 R61.2
N17709107: length 3
  TOP w0.102: U1.E1 20.15,34.11 18.72,34.11 18.54,34.3 17.85,34.3 R62.1
N17709123: length 3
  TOP w0.102: U1.F1 20.15,33.86 18.62,33.86 18.43,34.04 17.85,34.04 R63.1
N17709155: length 3.5
  TOP w0.15: U1.H1 19.84,32.36 18.04,30.57 R65.1
N17709188: length 6.6
  TOP w0.102: U1.A4 21.97,37.24 21.97,37.26 v1(21.97,37.26)
  BOTTOM w0.102: R66.2 19.05,40.13 19.25,40.33 19.63,40.33 19.79,40.18 20.09,40.18 20.24,40.33 20.58,40.33 21.01,39.9 21.01,39.42 20.85,39.27 20.85,38.96 21.01,38.81 21.01,38.43 21.61,37.82 22.05,37.82 22.2,37.67 22.2,37.49 v1(21.97,37.26)
N17709192: length 6.6
  TOP w0.102: U1.A5 v1(22.62,37.24)
  BOTTOM w0.102: R67.2 19.27,40.58 20.68,40.58 21.26,40 21.26,38.53 21.72,38.08 22.15,38.08 22.45,37.77 22.45,37.4 v1(22.62,37.24)
N17709220: length 4
  TOP w0.102: U1.A3 21.54,37.01 21.54,37.6 20.37,38.77 20.24,38.77 v2(19.99,39.02)
  BOTTOM w0.102: R68.2 19.31,38.81 19.78,38.81 v2(19.99,39.02)
N17709224: length 4
  TOP w0.102: U1.A2 21.13,36.91 21.29,37.06 21.29,37.49 20.26,38.51 20.09,38.51 19.99,38.41 v2(19.99,38.27)
  BOTTOM w0.102: v2(19.99,38.27) 19.99,38.41 19.84,38.56 19.31,38.56 19.05,38.3 R69.2
N17709256: length 4.1
  TOP w0.102: v1(21.96,36.6) 21.96,36.59 U1.B4
  BOTTOM w0.102: v1(21.96,36.6) 21.78,36.78 21.78,36.93 21.45,37.26 18.81,37.26 R70.2
N17709266: length 4.1
  TOP w0.102: U1.B3 21.32,36.59 21.32,36.61 v1(21.31,36.61)
  BOTTOM w0.102: v1(21.31,36.61) 21.32,36.61 21.34,36.59 21.41,36.59 21.53,36.7 21.53,36.83 21.35,37.01 18.95,37.01 18.74,36.8 R71.2
N17713383: length 2.4
  BOTTOM w0.15: R11.1 R10.2 11.11,8.8 11.38,9.06 11.81,9.06 11.98,9.24 U29.4
N17787194: length 2.1
  TOP w0.15: v2(24.18,7.75) 24.41,7.52 J1.A5
  BOTTOM w0.15: R4.1 24.28,7.24 24.18,7.34 v2(24.18,7.75)
N17787196: length 2
  TOP w0.15: J1.B5 v2(27.41,7.65)
  BOTTOM w0.15: R3.1 27.03,7.39 27.26,7.62 27.39,7.62 v2(27.41,7.65)
N17852597: length 1.3
  TOP w0.15: U21.5 16.79,10.23 16.81,10.26 R1.1
N17861601: length 0.9
  TOP w0.15: LED5.A 3.55,7.1 3.45,7.2 R159.1
N17865831: length 2.7
  BOTTOM w0.15: C27.2 R15.2 R16.1 U13.5
N17892556: length 17.7
  BOTTOM w0.089: 28.65,32.97 29.46,33.79 ; 23.95,33.22 24.44,33.71 25.02,33.71 25.08,33.65 26.4,33.65 27.08,32.97
  BOTTOM w0.102: 23.95,33.22 23.95,32.72 23.48,32.25 23.09,32.25 22.9,32.44 20.4,32.44 20.19,32.65 R218.1 ; TP52.1 29.46,36.8 29.46,33.79 ; 27.08,32.97 28.65,32.97
  BOTTOM w0.15: Y3.3 30.52,39.13 31.04,38.61 31.04,38.38 TP52.1
N17899696: length 1.2
  BOTTOM w0.15: R188.1 20.71,41.8 R189.2
N17920449: length 13.7
  TOP w0.127: C91.2 L3.2 30.33,51.84 arc(30.94,52.1) 31.19,52.71 31.19,54.07 31.19,54.07 ANT1.1
N17920453: length 2.6
  TOP w0.127: C91.1 L2.2 C90.2
N17920674: length 2.6
  TOP w0.127: C198.2 L6.2 C199.1
N17920680: length 3.3
  TOP w0.127: J12.S L7.2 C199.2
N17936697: length 6.3
  TOP w0.15: D11.A v2(19.51,4.07)
  BOTTOM w0.15: R174.1 17.6,1.45 17.73,1.32 19.33,1.32 19.79,1.79 19.79,3.78 v2(19.51,4.07)
N17936707: length 1.9
  TOP w0.15: D11.K 17.31,4.74 16.86,5.19 Q3.6
N17937120: length 2.3
  TOP w0.15: D14.A v2(19.23,2.41)
  BOTTOM w0.15: v2(19.23,2.41) 19.23,2.01 19.18,1.96 18.98,1.76 R190.1
N17937130: length 10.7
  TOP w0.15: D14.K 17.31,1.59 17.55,1.35 20.12,1.35 20.37,1.6 20.37,6.94 20.18,7.13 Q3.3
N17947353: length 1.6
  TOP w0.15: R182.1 29.36,47.44 29.41,47.49 Y4.O
N17989965: length 12
  TOP w0.102: R88.1 10.91,8.48 10.92,8.48 10.92,8.7 10.62,8.99 10.26,8.99 9.65,9.6 6.5,9.6 6.32,9.78 6.32,9.98 v2(6.57,10.23)
  BOTTOM w0.102: U8.3 2.62,8.61 2.52,8.71 2.52,9.07 2.62,9.17 6.07,9.17 6.32,9.42 6.32,9.98 v2(6.57,10.23)
N17989977: length 12
  TOP w0.102: R87.1 10.61,8.54 10.61,8.64 10.51,8.74 10.16,8.74 9.55,9.35 6.4,9.35 6.07,9.68 6.07,9.96 v2(5.8,10.23)
  BOTTOM w0.102: v2(5.8,10.23) 6.07,9.96 6.07,9.53 5.97,9.42 2.51,9.42 2.26,9.17 2.26,8.71 2.16,8.61 U8.1
N17990624: length 1.9
  BOTTOM w0.15: U7.3 34.06,8.87 33.92,9.01 33.92,9.74 34.17,9.99 R92.1
N17990639: length 1.9
  BOTTOM w0.15: R91.1 33.66,9.73 33.66,9.05 33.48,8.87 U7.1
N18038435: length 1.4
  TOP w0.15: LED1.A 29.3,11.19 29.05,10.94 R209.1
N18038437: length 1.5
  TOP w0.15: LED2.A 27.53,11.63 27.86,11.96 R210.1
N18038455: length 1.5
  TOP w0.15: Q7.D 30.85,9.31 30.58,9.59 30.16,9.59 30,9.75 30,9.79 29.97,9.82 LED1.K
N18038457: length 3.3
  TOP w0.15: LED2.K 27.04,10.19 26.78,10.46 26.78,10.61 v2(26.49,10.9)
  BOTTOM w0.15: Q8.D 25.99,9.59 26.49,10.1 v2(26.49,10.9)
N18039037: length 1.1
  TOP w0.15: LED3.1 32.33,10.4 32.17,10.24 R156.2
N18039056: length 1.1
  TOP w0.15: LED3.2 32.27,11.3 32.22,11.25 R157.2
N18039072: length 1.8
  TOP w0.15: v2(35.23,11.25) 35.19,11.3 LED3.3
  BOTTOM w0.15: R165.1 34.63,11.43 34.65,11.44 35.04,11.44 v2(35.23,11.25)
N18042757: length 1
  BOTTOM w0.15: U40.5 14.7,47.43 14.65,47.38 R217.1
N18094677: length 32.4
  TOP w0.15: U20.A2 18.47,26.7 18.72,26.44 v2(18.72,25.73)
  L03_SIG1 w0.157: v2(18.72,25.73) 17.98,26.47 17.03,26.47 15.86,27.64 11.54,27.64 10.14,29.04 10.14,30.88 8.71,32.31 8.71,34.95 8.45,35.21 8.45,36.56 8.26,36.76 8.26,41.17 6.63,42.8 6.63,47.01 6.65,47.04 v2(6.65,47.45)
  BOTTOM w0.15: R220.1 7.09,47.32 6.94,47.47 6.68,47.47 v2(6.65,47.45)
N18094686: length 29.6
  TOP w0.15: v2(18.06,25.66) 18.06,26.09 U20.A3
  L03_SIG1 w0.157: v2(18.06,25.66) 17.48,25.66 15.75,27.38 11.43,27.38 9.88,28.93 9.88,30.62 7.88,32.62 7.88,35.86 7.69,36.05 7.69,37.1 7.95,37.36 7.95,41.02 6.07,42.9 v2(6.07,44.78)
  BOTTOM w0.15: v2(6.07,44.78) 6.49,44.78 7.05,45.35 R222.1
N18095156: length 1
  TOP w0.15: U20.C2 16.75,26.7 16.55,26.5 16.55,26.49 16.51,26.45 C69.1

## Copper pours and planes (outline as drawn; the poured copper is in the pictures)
GND_EARTH on TOP: 5.21,7.44 6.3,7.44 6.65,7.09 6.65,6.17 6.73,6.1 6.58,6.1 6.58,5.23 6.88,5.23 6.88,3.73 7.8,2.82 12.88,2.82 13.41,3.35 15.16,3.35 15.88,2.64 15.88,0.84 15.61,0.57 15,0.57 14.99,0.56 5.23,0.56 5.11,0.69 5.11,7.34
GND_EARTH on BOTTOM: 21.11,7.67 22.43,7.67 22.61,7.49 22.61,2.06 23.12,1.55 28.4,1.55 28.7,1.86 28.7,4.8 29.08,5.18 29.08,5.21 29.41,5.21 29.41,5.87 29.08,5.87 29.08,7.42 29.29,7.62 30.79,7.62 30.99,7.42 30.99,0.64 30.89,0.53 13.18,0.53 13,0.71 13,1.35 13.18,1.53 13.18,7.29 13.46,7.57 15.42,7.57 15.72,7.27 15.72,3.86 15.9,3.68 17.55,3.68 17.63,3.76 18.69,3.76 18.77,3.68 18.77,2.85 18.67,2.74 17.27,2.74 17.22,2.69 17.22,1.42 17.45,1.19 19.53,1.19 19.99,1.65 19.99,3.89 20.09,3.99 20.09,7.24 20.22,7.37 20.27,7.42 20.85,7.42 ; 3 cut-outs
GND_EARTH on BOTTOM: 5.05,7.67 6.65,7.67 7.06,7.27 7.06,5.89 6.55,5.89 6.55,5.21 7.06,5.21 7.06,2.49 7.42,2.13 7.42,0.61 7.37,0.56 5.33,0.56 4.75,1.14 4.75,7.37
GND_SIGNAL on BOTTOM (solid shape): outline of 128 points within 1.35,5.39 3.43,7.47
GND_SIGNAL on BOTTOM (solid shape): outline of 128 points within 1.66,52.13 3.74,54.21
GND_SIGNAL on BOTTOM (solid shape): outline of 128 points within 32.72,5.65 34.8,7.73
GND_SIGNAL on BOTTOM (solid shape): outline of 128 points within 32.77,52.13 34.85,54.21
GND_SIGNAL on TOP: 21.73,7.35 21.17,7.35 20.98,7.55 20.98,8.36 21.06,8.43 22.05,8.43 22.2,8.28 22.2,7.75 22.61,7.34 22.73,7.34 22.76,7.32 22.76,6.12 22.73,6.1 22.15,6.1 22.12,6.12 22.12,6.96
GND_SIGNAL on TOP: 28.58,6.07 29.24,6.07 29.26,6.1 29.26,7.06 29.85,7.65 29.69,7.8 29.69,8.08 29.64,8.13 29.18,8.13 29.06,8 28.65,8 28.5,7.85 28.5,7.32 28.55,7.27 28.55,6.1
GND_SIGNAL on BOTTOM: 2.92,12.45 3.02,12.35 4.24,12.35 4.34,12.24 4.34,10.59 3.86,10.11 0.66,10.11 0.56,10.21 0.56,12.32 0.58,12.35 1.17,12.35 1.4,12.57 1.4,16.49 1.3,16.59 0.58,16.59 0.53,16.64 0.53,18.64 0.61,18.72 5,18.72 5.11,18.62 5.11,16.71 4.9,16.51 3.15,16.51 2.92,16.28
GND_SIGNAL on BOTTOM: 24.82,12.65 25,12.47 25,11.23 24.84,11.08 24.46,11.08 24.06,10.67 23.98,10.67 23.62,11.02 23.62,11.05 24.06,11.48 24.06,12.14 24.18,12.27 24.18,13.41 24.23,13.46 24.79,13.46 24.82,13.44
GND_SIGNAL on BOTTOM: 22.4,10.95 22.73,11.28 22.73,12.88 22.63,12.98 21.54,12.98 21.46,12.9 21.46,11.66 21.39,11.58 21.39,11.35 20.98,10.95 20.98,10.9 21.29,10.59 21.39,10.59 21.74,10.95
GND_SIGNAL on L02_GND: 0.53,61.5 0.96,62.53 2,62.96 33.99,62.96 35.03,62.53 35.46,61.5 35.46,23.07 32.92,23.07 32.92,21.5 35.46,21.5 35.46,18.5 35.41,18.44 32.97,18.44 32.92,18.39 32.92,17.07 32.59,17.07 32.59,16.92 32.92,16.92 32.92,16.46 33.02,16.36 35.41,16.36 35.46,16.3 35.46,13.68 32.89,13.68 32.89,11.94 32.94,11.89 35.38,11.89 35.46,11.81 35.46,2 35.03,0.96 33.99,0.53 2,0.53 0.96,0.96 0.53,2 0.53,14.28 1.24,14.28 1.24,14.58 0.53,14.58 0.53,18.87 1.14,18.87 1.14,19.41 0.53,19.41 0.53,20.3 1.09,20.3 1.09,21.31 0.53,21.31 ; 95 cut-outs
GND_SIGNAL on L05_PWR: 33.25,45.82 35.31,45.82 35.31,45.8 35.48,45.62 35.48,44.6 35.2,44.32 35.2,43 35.48,42.72 35.48,32.72 35.49,32.71 35.49,29.41 35.36,29.41 34.98,29.03 34.98,28.65 35.48,28.14 35.49,28.14 35.49,24.89 34.46,23.87 33.82,23.87 33.8,23.89 32.59,23.89 32.09,23.4 31.79,23.4 31.15,22.77 31.15,21.62 30.43,21.62 29.18,22.86 29.18,24.31 29.95,25.07 29.95,29.44 32.31,31.8 32.31,33.07 31.85,33.53 29.97,33.53 29.57,33.94 29.57,37.47 29.54,37.49 27.76,37.49 27.61,37.64 27.61,40.01 27.79,40.18 29.92,40.18 33.12,43.38 33.12,45.7 ; 5 cut-outs
GND_SIGNAL on L05_PWR: 0.58,61.97 1.13,62.71 2,62.99 23.5,62.99 23.57,62.92 23.57,55.12 23.77,54.92 34.82,54.92 35.38,54.36 35.38,51.77 34.67,51.06 17.12,51.06 14.76,48.69 14.05,48.69 12.93,47.58 10.77,47.58 10.24,48.11 4.95,48.11 4.39,47.55 0.71,47.55 0.58,47.68 ; 1 cut-out
VBAT_IN on TOP: 9.42,13.49 9.5,13.56 11.15,13.56 11.18,13.54 12.12,13.54 12.17,13.59 12.17,14.71 11.86,15.01 10.03,15.01 9.42,15.62 9.42,15.88 8.97,16.33 6.32,16.33 5.21,15.22 5.21,13.62 5.33,13.49
VBAT_IN on BOTTOM: 9.5,16.71 9.53,16.69 9.53,16.08 9.58,16.03 10.03,16.03 10.11,16.1 10.11,16.64 10.16,16.69 10.34,16.69 10.49,16.69 10.52,16.66 10.52,15.8 10.44,15.72 9.91,15.72 9.53,15.34 9.53,13.79 9.4,13.67 8.33,13.67 8.28,13.72 8.28,14.91 8.54,15.16 8.99,15.16 9.09,15.27 9.09,15.72 8.99,15.83 8.33,15.83 8.26,15.9 8.26,16.66 8.31,16.71
VCC_1V8 on BOTTOM: 23.95,13.06 23.85,12.96 23.85,11.48 23.62,11.25 23.06,11.25 22.94,11.38 22.94,14.07 23.27,14.4 23.9,14.4 23.95,14.35
VCC_1V8 on L04_SIG2: 22.18,13.72 26.01,13.72 28.07,11.66 28.07,10.14 28.02,10.08 27.25,10.08 27.1,9.93 20.07,9.93 19.92,9.78 19.92,7.9 19.71,7.7 18.7,7.7 18.62,7.77 18.62,9.09 18.72,9.2 18.72,11.06 18.54,11.24 18.54,13.29 18.62,13.36 21.82,13.36
VCC_3V3 on BOTTOM: 20.93,11.1 21.19,11.35 21.19,14.05 21.03,14.2 20.37,14.2 20.27,14.1 20.27,13.03 19.89,12.65 19.89,12.22 20.37,11.74 20.37,11.15 20.42,11.1
VCC_IN on TOP: 23.24,9.15 22.25,9.15 22.07,8.97 21.46,8.97 21.39,9.04 21.39,9.65 21.54,9.81 24.03,9.81 24.08,9.75 24.08,9.35 24.03,9.3 23.39,9.3
VCC_IN on BOTTOM: 9.65,19.66 9.73,19.58 9.73,18.9 9.55,18.72 9.55,18.26 9.53,18.24 9.53,18.09 9.47,18.04 8.53,18.04 8.33,18.24 8.33,19.58 8.41,19.66
VCC_IN on BOTTOM: 13.9,17.91 13.39,17.91 13.03,18.26 12.04,18.26 11.96,18.19 11.96,17.53 12.09,17.4 13.82,17.4 13.92,17.5 13.92,17.88
VCC_IN on BOTTOM: 12.09,11.66 12.3,11.46 12.3,10.97 12.22,10.9 11.76,10.9 11.74,10.92 10.26,10.92 10.16,10.82 8.87,10.82 8.79,10.9 8.79,12.75 10.72,14.68 10.72,16.1 10.77,16.16 12.02,16.16 12.09,16.08
VCC_IN on L04_SIG2: 12.55,13.51 13.49,13.51 13.92,13.08 13.92,10.69 15.32,9.3 15.32,8.26 15.9,7.67 17.25,7.67 17.32,7.6 18.95,7.6 19.18,7.82 19.18,10.06 19.99,10.87 22.38,10.87 22.66,10.59 22.66,9.73 25.98,9.73 26.54,9.17 26.54,3.25 26.31,3.02 24.21,3.02 23.39,2.21 12.45,2.21 12.45,2.52 12.09,2.52 12.09,2.21 6.58,2.21 4.93,3.86 4.93,11.46 5.59,12.12 8.38,12.12 9.22,12.96 9.22,13.31 9.4,13.49 12.52,13.49 ; 4 cut-outs
VCC_IN on L05_PWR: 13.29,17.42 13.29,12.85 12.83,12.4 8.84,12.4 8.84,12.4 6.99,12.4 5.77,13.62 5.77,19 6.45,19.69 11.02,19.69
VDD_1V8 on BOTTOM: 6.28,21.74 6.28,22.84 6.35,22.91 7.21,22.91 7.52,23.22 7.8,23.22 8.1,22.91 10.72,22.91 10.8,22.84 10.8,22.48 10.72,22.4 9.09,22.4 8.89,22.2 8.89,21.74 8.86,21.72 8.2,21.72 7.98,21.49 6.53,21.49
VDD_1V8 on BOTTOM: 10.8,28.91 10.8,28.12 10.85,28.07 11.66,28.07 12.35,27.38 12.35,27.05 12.4,27 13.21,27 13.26,27.05 13.26,27.53 12.83,27.97 12.55,27.97 12.45,28.07 12.45,29.36 12.63,29.54 12.85,29.54 12.98,29.67 12.98,30.25 12.93,30.3 12.04,30.3 11.71,29.97 11.71,29.49 11.74,29.47 11.74,29.13 11.61,29.01 10.9,29.01
VDD_1V8 on L04_SIG2: 15.34,27.92 15.6,27.66 16.89,27.66 17.35,27.2 17.35,24.72 17.3,24.66 17.3,24.16 17.02,24.16 16.41,23.55 16.41,22.66 16.54,22.53 18.11,22.53 18.12,22.54 18.24,22.43 18.8,22.43 19.08,22.71 21.16,22.71 21.44,22.99 21.44,26.37 20.98,26.82 18.92,26.82 18.03,27.71 17.83,27.71 17.37,28.17 17.37,28.45 17.22,28.6 15.52,28.6 15.34,28.42
VDD_1V8 on L05_PWR: outline of 105 points within 0.51,1.27 35.48,51.64 ; 14 cut-outs
VDD_3V3 on BOTTOM: 5.71,24.18 5.99,23.9 6.68,23.9 6.73,23.95 6.73,24.36 6.86,24.49 6.86,25.86 6.78,25.93 6.25,25.93 6.15,25.83 6.15,25.66 6.05,25.55 5.87,25.55 5.71,25.4
VDD_3V3 on BOTTOM: 18.06,29.44 19.03,29.44 19.1,29.36 19.1,29.13 19.23,29.01 19.23,28.12 19.64,27.71 19.64,27.08 19.33,26.77 18.77,26.77 18.7,26.85 18.7,27.36 18.59,27.46 18.59,28.09 17.63,28.09 17.5,27.97 17.5,27.59 17.4,27.48 16.23,27.48 16.08,27.64 16.08,30.63 16.21,30.76 16.21,31.37 16.26,31.42 17.17,31.42 17.25,31.34 17.25,30.25
VDD_3V3 on BOTTOM: 22.94,10.92 23.55,10.92 23.9,10.57 24.11,10.57 24.41,10.87 24.51,10.87 24.56,10.82 24.56,10.57 23.39,9.4 23.39,8.46 23.29,8.36 22.71,8.36 22.58,8.48 22.58,9.19 22.84,9.45 22.84,10.82
VDD_3V3 on L03_SIG1: 5.08,25.05 6.4,25.05 6.53,24.92 6.53,20.83 4.72,19.03 4.72,15.44 5.46,14.71 5.46,13.13 6.32,12.27 15.85,12.27 17.22,10.9 18.65,10.9 19.33,11.58 22.99,11.58 23.34,11.23 23.45,11.23 23.93,10.75 23.93,9.91 23.47,9.45 21.77,9.45 21.69,9.37 19.89,9.37 19.61,9.09 18.11,9.09 17.65,9.55 16.75,9.55 16.38,9.92 11.72,9.92 10.97,9.17 4.19,9.17 2.9,10.47 2.9,18.49 3.3,18.9 3.3,21.57 3.4,21.67 3.4,21.16 3.73,21.16 3.73,22 4.95,23.22 4.95,24.92 ; 3 cut-outs
VDD_3V3 on L04_SIG2: outline of 98 points within 5.44,24.21 26.29,57.07 ; 18 cut-outs
VDD_3V3 on L04_SIG2: 19.25,28.78 19.25,28.27 20.09,27.43 20.09,27.15 19.81,26.87 19.15,26.87 18.11,27.92 17.86,27.92 17.58,28.2 17.58,28.8 17.65,28.88 19.15,28.88
VDD_5V on TOP: 13.69,9.55 13.92,9.55 13.95,9.58 14.63,9.58 14.66,9.55 14.66,8.79 14.4,8.54 13.69,8.54 13.36,8.87 12.9,8.87 12.88,8.89 12.88,9.2 12.93,9.25 13.39,9.25
VDD_5V on TOP: 2.59,59.39 2.59,56.52 2.77,56.34 3.71,56.34 3.81,56.44 3.81,59.34 3.68,59.46 2.67,59.46
VDD_5V on TOP: 6.99,28.53 6.5,28.04 6.5,27.36 6.78,27.08 6.93,27.08 6.99,27.03 6.99,26.42 6.91,26.34 6.4,26.34 6.25,26.49 6.25,26.93 5.61,27.56 5.21,27.56 5.03,27.74 5.03,29.64 5.44,30.05 5.44,31.55 5.49,31.6 6.81,31.6 6.99,31.42
VDD_5V on BOTTOM: 16.89,25.86 16.92,25.88 17.45,25.88 17.53,25.81 17.53,24.69 17.5,24.66 17.5,24.28 17.6,24.18 17.6,23.12 17.53,23.04 16.94,23.04 16.79,23.19 16.79,23.42 16.89,23.52 16.89,24.54 16.54,24.89 16.23,24.89 16.13,24.99 16.13,25.45 16.16,25.48 16.87,25.48 16.89,25.5
VDD_5V on BOTTOM: 11.18,21.18 12.88,21.18 13,21.31 13,22.23 12.93,22.3 11.33,22.3 10.79,21.77 10.39,21.77 10.31,21.85 10.31,22.12 10.39,22.2 10.39,22.2 10.85,22.2 11.48,22.84 13.67,22.84 13.92,22.58 13.92,20.04 13.92,20.04 13.92,19.97 13.72,19.76 11.81,19.76 10.95,20.63 10.39,20.63 10.34,20.68 10.34,21.01 10.36,21.03 11.03,21.03
VDD_5V on BOTTOM: 19.86,10.8 21.01,10.8 21.36,10.44 21.44,10.44 21.74,10.75 21.92,10.75 21.95,10.72 21.95,10.21 21.74,10.01 21.39,10.01 21.39,10.01 20.75,10.01 20.52,9.78 20.52,8.99 20.85,8.66 20.85,7.82 20.8,7.77 20.04,7.77 19.94,7.88 19.94,8.15 19.66,8.43 19.23,8.43 18.98,8.18 18.26,8.18 18.14,8.31 15.95,8.31 15.7,8.56 12.83,8.56 12.73,8.46 12.12,8.46 11.84,8.18 11.61,8.18 11.58,8.21 11.58,8.71 11.71,8.84 11.93,8.84 12.06,8.98 12.38,8.98 12.83,9.42 12.83,9.88 12.9,9.96 14.4,9.96 14.61,10.16 19.25,10.16 19.25,10.19
VDD_5V on BOTTOM: 2.79,56.26 2.72,56.34 2.72,59.28 2.77,59.34 7.42,59.34 7.7,59.61 9.17,59.61 9.3,59.49 9.3,56.44 9.12,56.26
VDD_5V on L03_SIG1: 2.82,57.28 4.65,57.28 5.13,56.8 5.13,51.97 7.59,49.51 7.59,36.3 7.85,36.04 7.85,33.02 7.61,32.78 7.05,32.78 6.68,32.41 6.68,32.13 6.81,32.01 6.81,31.27 6.27,30.74 5.05,30.74 4.65,31.14 4.65,38 5.21,38.56 5.21,38.81 4.5,39.52 4.5,48.77 2.39,50.88 2.39,56.85 ; 1 cut-out
VDD_5V on L05_PWR: outline of 84 points within 4.78,7.16 29.01,29.72 ; 9 cut-outs
VDDIO_RADIO on BOTTOM: 28.22,48.01 29.13,48.01 29.39,48.26 29.39,50.55 29.24,50.7 28.37,50.7 28.17,50.9 28.17,51.28 28.12,51.33 27.91,51.33 27.89,51.31 27.89,51.21 27.89,51.21 27.89,50.04 27.79,49.94 27.79,49.45 27.69,49.35 26.62,49.35 26.42,49.15 20.32,49.15 20.22,49.25 20.22,49.66 20.12,49.76 19.2,49.76 19.1,49.66 19.1,48.34 18.69,47.93 18.69,44.35 19.25,43.79 21.18,43.79 21.56,44.17 21.56,46.13 21.82,46.38 22.05,46.38 22.1,46.43 22.1,46.81 22.78,47.5 27.71,47.5
